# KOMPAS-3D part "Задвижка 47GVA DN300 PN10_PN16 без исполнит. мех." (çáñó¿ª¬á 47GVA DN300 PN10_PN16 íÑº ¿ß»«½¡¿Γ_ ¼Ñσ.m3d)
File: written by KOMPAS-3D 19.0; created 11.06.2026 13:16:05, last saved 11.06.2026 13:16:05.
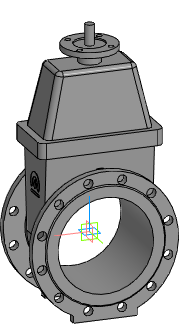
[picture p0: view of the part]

Document properties: Автор: Евгений; Полное имя файла: Z:\3.Личные\kachalov\001_3d для проектировщиков\2.2 Тип 47GVA, 47GVA.Z\_stp\_stp_Задвижка 47GVA DN40-DN1000 без исп.мех\Задвижка 47GVA DN300 PN10_PN16 без исполнит_ мех.m3d

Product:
- Part/product: Задвижка 47GVA DN300 PN10_PN16 без исполнит. мех.

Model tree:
1. Операция без истории:1  (labels: Задвижка 47GVA DN300 PN10_PN16 без исполнит. мех.)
